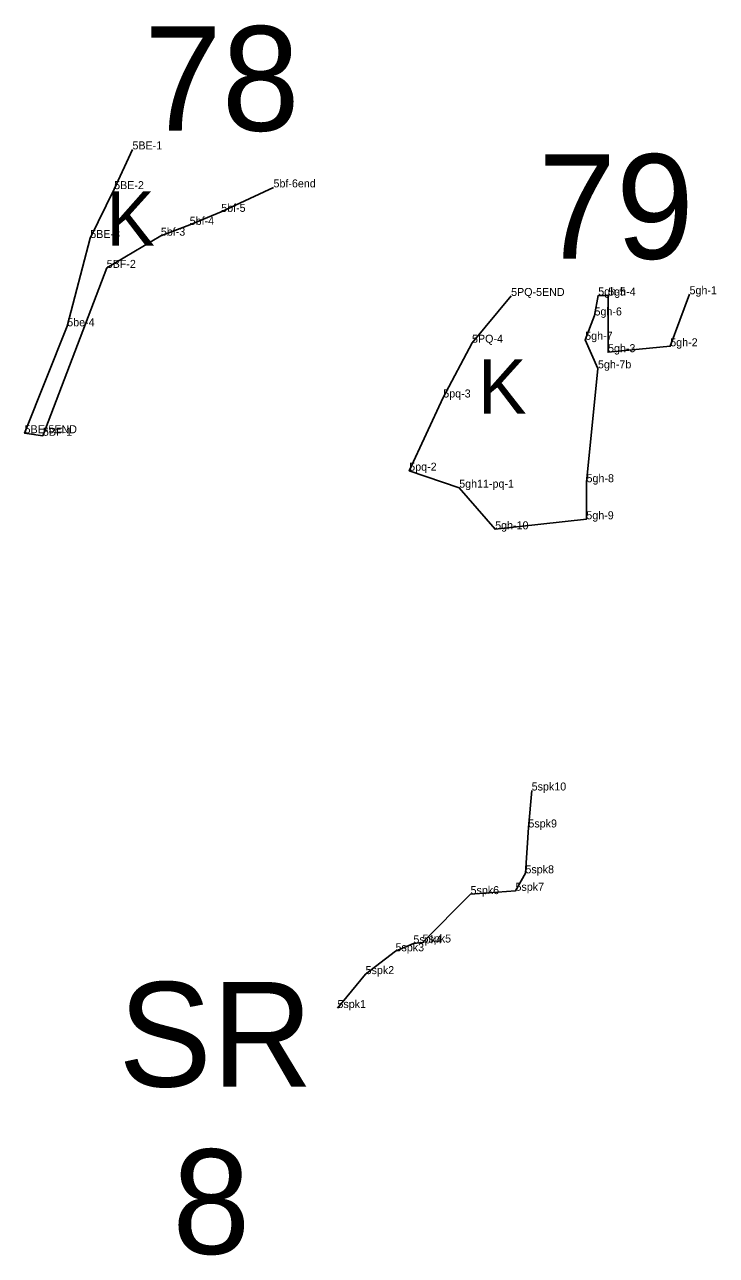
# Model space of a CAD drawing. Extents: x 2072529 to 2268796, y 436423 to 470406.
# Drawn here: x 2120838 to 2121270, y 448466 to 449235 of the extents above; entities that cross this region are included whole.
import ezdxf

# ---------------------------------------------------------------- set-up
doc = ezdxf.new("R2010")
doc.units = 0
for name, color, linetype in [('Default', 7, 'Continuous'), ('Exist Environmental Wetland Boundary', 7, 'Continuous'), ('Exist Environmental Wetland Boundary Cogo Comment', 7, 'Continuous'), ('Exist Hydro Jurisdictional Stream or Body of Water NEU Mitigable', 7, 'Continuous'), ('Exist Hydro Jurisdictional Stream or Body of Water NEU Mitigable Cogo Comment', 7, 'Continuous'), ('Exist Hydro Swamp or Marsh', 7, 'Continuous'), ('Old_Level_20', 7, 'Continuous')]:
    doc.layers.add(name, color=color, linetype=linetype)

msp = doc.modelspace()

# ---------------------------------------------------------------- linework, layer by layer
at = {"layer": 'Exist Environmental Wetland Boundary'}
for points in [[(2120904.9, 449157.04), (2120893.47, 449132.19), (2120878.54, 449101.66), (2120864.15, 449046.5), (2120837.53, 448979.65), (2120848.98, 448978.07)], [(2120993.04, 449133.29), (2120960.35, 449117.99), (2120940.67, 449109.9), (2120922.64, 449103.11), (2120888.83, 449082.98), (2120848.98, 448978.07)], [(2121141.49, 449065.44), (2121117.07, 449036.22), (2121099.11, 449001.99), (2121077.84, 448956.25), (2121109.06, 448945.63), (2121131.53, 448919.61), (2121188.51, 448925.88), (2121188.65, 448949.04), (2121195.78, 449020.2), (2121187.81, 449038.05), (2121193.61, 449053.26), (2121195.96, 449065.76), (2121202.21, 449065.68), (2121202.06, 449030.31), (2121240.94, 449033.98), (2121252.98, 449066.51)]]:
    msp.add_lwpolyline(points, dxfattribs=at)
at = {"layer": 'Exist Hydro Jurisdictional Stream or Body of Water NEU Mitigable'}
msp.add_lwpolyline([(2121154.35, 448756.4), (2121152.3, 448733.29), (2121150.45, 448704.64), (2121144.24, 448693.72), (2121116.15, 448691.64), (2121086.13, 448661.4), (2121080.45, 448660.87), (2121069.27, 448655.91), (2121050.58, 448641.64), (2121032.99, 448620.46)], dxfattribs=at)
at = {"layer": 'Old_Level_20'}
for p, q in [((2120904.9, 449157.04), (2120904.9, 449157.04)), ((2120893.47, 449132.19), (2120893.47, 449132.19)), ((2120993.04, 449133.29), (2120993.04, 449133.29)), ((2120960.35, 449117.99), (2120960.35, 449117.99)), ((2120940.67, 449109.9), (2120940.67, 449109.9)), ((2120878.54, 449101.66), (2120878.54, 449101.66)), ((2120922.64, 449103.11), (2120922.64, 449103.11)), ((2120888.83, 449082.98), (2120888.83, 449082.98)), ((2121141.49, 449065.44), (2121141.49, 449065.44)), ((2121195.96, 449065.76), (2121195.96, 449065.76)), ((2121202.21, 449065.68), (2121202.21, 449065.68)), ((2121252.98, 449066.51), (2121252.98, 449066.51)), ((2121193.61, 449053.26), (2121193.61, 449053.26)), ((2120864.15, 449046.5), (2120864.15, 449046.5)), ((2121187.81, 449038.05), (2121187.81, 449038.05)), ((2121117.07, 449036.22), (2121117.07, 449036.22)), ((2121202.06, 449030.31), (2121202.06, 449030.31)), ((2121240.94, 449033.98), (2121240.94, 449033.98)), ((2121195.78, 449020.2), (2121195.78, 449020.2)), ((2121099.11, 449001.99), (2121099.11, 449001.99)), ((2120848.98, 448978.07), (2120848.98, 448978.07)), ((2121077.84, 448956.25), (2121077.84, 448956.25)), ((2121109.06, 448945.63), (2121109.06, 448945.63)), ((2121188.65, 448949.04), (2121188.65, 448949.04)), ((2121188.51, 448925.88), (2121188.51, 448925.88)), ((2121131.53, 448919.61), (2121131.53, 448919.61)), ((2121154.35, 448756.4), (2121154.35, 448756.4)), ((2121152.3, 448733.29), (2121152.3, 448733.29)), ((2121150.45, 448704.64), (2121150.45, 448704.64)), ((2121116.15, 448691.64), (2121116.15, 448691.64)), ((2121144.24, 448693.72), (2121144.24, 448693.72)), ((2121080.45, 448660.87), (2121080.45, 448660.87)), ((2121086.13, 448661.4), (2121086.13, 448661.4)), ((2121069.27, 448655.91), (2121069.27, 448655.91)), ((2121050.58, 448641.64), (2121050.58, 448641.64)), ((2121032.99, 448620.46), (2121032.99, 448620.46))]:
    msp.add_line(p, q, dxfattribs=at)
msp.add_lwpolyline([(2120837.53, 448979.65), (2120837.53, 448979.65), (2120837.53, 448979.65)], dxfattribs=at)

# ---------------------------------------------------------------- texts
at = {"layer": 'Default'}
for s, p in [('78', (2120912.16, 449168.7)), ('79', (2121158.5, 449088.68)), ('SR', (2120896.18, 448571.34)), ('8', (2120929.86, 448466.8))]:
    msp.add_text(s, height=65.34, dxfattribs=at).set_placement(p)
at = {"layer": 'Exist Environmental Wetland Boundary Cogo Comment'}
for s, p in [('5BE-1', (2120904.9, 449157.04)), ('5BE-2', (2120893.47, 449132.19)), ('5bf-6end', (2120993.04, 449133.29)), ('5bf-5', (2120960.35, 449117.99)), ('5bf-4', (2120940.67, 449109.9)), ('5BE-3', (2120878.54, 449101.66)), ('5bf-3', (2120922.64, 449103.11)), ('5BF-2', (2120888.83, 449082.98)), ('5PQ-5END', (2121141.49, 449065.44)), ('5gh-5', (2121195.96, 449065.76)), ('5gh-4', (2121202.21, 449065.68)), ('5gh-1', (2121252.98, 449066.51)), ('5gh-6', (2121193.61, 449053.26)), ('5be-4', (2120864.15, 449046.5)), ('5PQ-4', (2121117.07, 449036.22)), ('5gh-7', (2121187.81, 449038.05)), ('5gh-2', (2121240.94, 449033.98)), ('5gh-3', (2121202.06, 449030.31)), ('5gh-7b', (2121195.78, 449020.2)), ('5pq-3', (2121099.11, 449001.99)), ('5BE-5END', (2120837.53, 448979.65)), ('5BF-1', (2120848.98, 448978.07)), ('5pq-2', (2121077.84, 448956.25)), ('5gh-8', (2121188.65, 448949.04)), ('5gh11-pq-1', (2121109.06, 448945.63)), ('5gh-9', (2121188.51, 448925.88)), ('5gh-10', (2121131.53, 448919.61))]:
    msp.add_text(s, height=5, dxfattribs=at).set_placement(p)
at = {"layer": 'Exist Hydro Jurisdictional Stream or Body of Water NEU Mitigable Cogo Comment'}
for s, p in [('5spk10', (2121154.35, 448756.4)), ('5spk9', (2121152.3, 448733.29)), ('5spk8', (2121150.45, 448704.64)), ('5spk7', (2121144.24, 448693.72)), ('5spk6', (2121116.15, 448691.64)), ('5spk3', (2121069.27, 448655.91)), ('5spk4', (2121080.45, 448660.87)), ('5spk5', (2121086.13, 448661.4)), ('5spk2', (2121050.58, 448641.64)), ('5spk1', (2121032.99, 448620.46))]:
    msp.add_text(s, height=5, dxfattribs=at).set_placement(p)
at = {"layer": 'Exist Hydro Swamp or Marsh'}
for p in [(2120888.58, 449096.87), (2121120.84, 448991.88)]:
    msp.add_text('K', height=34, dxfattribs=at).set_placement(p)

doc.saveas('drawing.dxf')
